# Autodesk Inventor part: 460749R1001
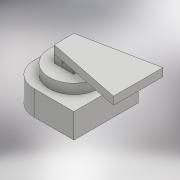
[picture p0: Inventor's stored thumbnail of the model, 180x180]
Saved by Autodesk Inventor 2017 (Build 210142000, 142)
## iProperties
Created: 2016-07
Part Number: 460749R1001
Material: Generic
Document SubType Name: Modeling
Designer: Polytech
Density: 1 g/cm^3
Appearance: Default
Author: Polytech
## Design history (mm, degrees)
sketch "Sketch1"
  geometry: C1 r 23 at (0, 0); 1 further point
  constraints: 1 centre point, 1 coincident
  dimensions: "d0" = 46 diameter of C1
extrude "Extrusion1" new body sketch "Sketch1" distance "d1" = 18; taper "d2" = 0 deg
sketch "Sketch2"
  geometry: L1 (-11.75, -48.75)-(48.75, -48.75); L2 (48.75, -48.75)-(48.75, 48.75); L3 (48.75, 48.75)-(-11.75, 48.75); L4 (-48.75, 11.75)-(-48.75, -11.75); L5 (-48.75, -48.75)-(48.75, 48.75); L6 (48.75, -48.75)-(-48.75, 48.75); A1 r 37 centre (-11.75, 11.75) between (-11.75, 48.75) and (-48.75, 11.75); A2 r 37 centre (-11.75, -11.75) between (-48.75, -11.75) and (-11.75, -48.75); 1 further point
  constraints: 12 end point, 4 point on circle, 4 point on line, 4 tangent, 2 centre point, 2 midpoint, 2 parallel, 1 equal radius, 1 horizontal, 1 perpendicular
  dimensions: "d3" = 97.5 distance of L6.end L2.end; "d4" = 97.5 distance of L2.end L1.end; "d5" = 37 radius of A1
extrude "Extrusion2" join sketch "Sketch2" distance "d6" = 37.5; taper "d7" = 0 deg
sketch "Sketch3"
  geometry: C1 r 37.5 at (0, 0); 1 further point
  constraints: 1 centre point, 1 coincident
  dimensions: "d8" = 75 diameter of C1
extrude "Extrusion3" join sketch "Sketch3" distance "d9" = 15; taper "d10" = 0 deg
sketch "Sketch4"
  geometry: L1 (-15, -15)-(15, -15); L2 (15, -15)-(15, 15); L3 (15, 15)-(-15, 15); L4 (-15, 15)-(-15, -15); L5 (-15, -15)-(15, 15); L6 (15, -15)-(-15, 15); 1 further point
  constraints: 12 end point, 2 midpoint, 2 parallel, 1 horizontal, 1 perpendicular
  dimensions: "d11" = 30 distance of L3.end L2.end; "d12" = 30 distance of L2.end L1.end
extrude "Extrusion4" join sketch "Sketch4" distance "d13" = 12; taper "d14" = 0 deg
sketch "Sketch5"
  geometry: L1 (-15, 6)-(15, 6); L2 (15, 6)-(15, -6); L3 (15, -6)-(-15, -6); L4 (-15, -6)-(-15, 6); L5 (-15, 6)-(15, -6); L6 (15, 6)-(-15, -6); 1 further point
  constraints: 12 end point, 2 midpoint, 2 parallel, 1 horizontal, 1 perpendicular
  dimensions: "d15" = 30 distance of L2.end L3.end; "d16" = 12 distance of L1.end L2.end
extrude "Extrusion5" cut sketch "Sketch5" distance "d17" = 12; taper "d18" = 0 deg
sketch "Sketch6"
  geometry: L1 (52.5, 0)-(-22.5, 0) reference; C1 r 3 at (15, 6); 1 further point
  constraints: 1 centre point, 1 vertical alignment
  dimensions: "d19" = 6 diameter of C1; "d20" = 6 distance from line of L1 C1.centre
extrude "Extrusion6" cut sketch "Sketch6" stored distance "d21" = 12; taper "d22" = 0 deg
sketch "Sketch7"
  geometry: L1 (-15, 15)-(-15, -15); L2 (-15, -15)-(97.5, -37.5); L3 (97.5, -37.5)-(97.5, 37.5); L4 (97.5, 37.5)-(-15, 15); 4 further points
  constraints: 8 end point, 2 coincident, 1 horizontal alignment, 1 midpoint, 1 parallel, 1 vertical
  dimensions: "d23" = 97.5 distance from line of L3 point (0, 0); "d24" = 75 distance of L2.end L3.end
extrude "Extrusion7" join sketch "Sketch7" distance "d25" = 12; taper "d26" = 0 deg
sketch "Sketch8"
  geometry: C1 r 23 at (0, 0); 1 further point
  constraints: 1 centre point, 1 coincident
  dimensions: "d27" = 46 diameter of C1
extrude "Extrusion8" cut sketch "Sketch8" distance "d28" = 24.5; taper "d29" = 0 deg
body "Solid1"
